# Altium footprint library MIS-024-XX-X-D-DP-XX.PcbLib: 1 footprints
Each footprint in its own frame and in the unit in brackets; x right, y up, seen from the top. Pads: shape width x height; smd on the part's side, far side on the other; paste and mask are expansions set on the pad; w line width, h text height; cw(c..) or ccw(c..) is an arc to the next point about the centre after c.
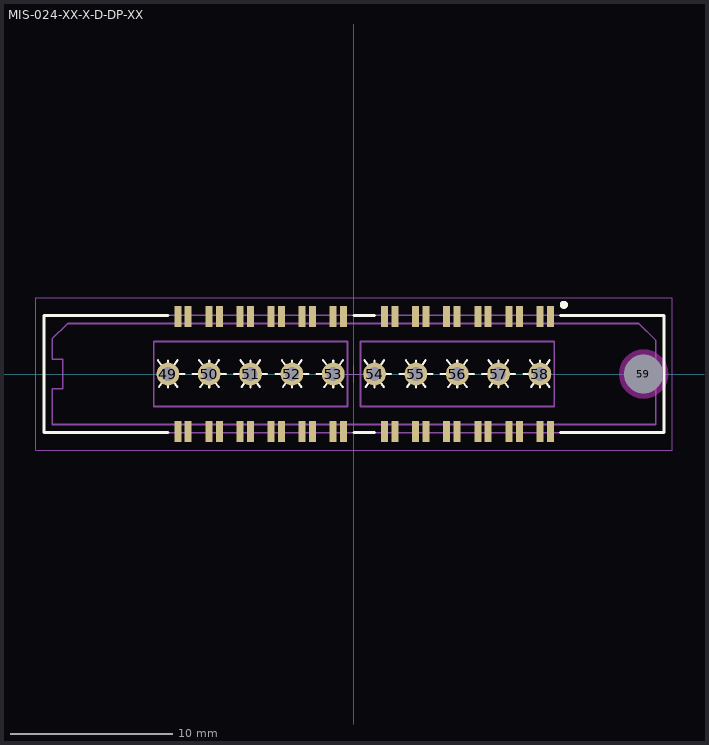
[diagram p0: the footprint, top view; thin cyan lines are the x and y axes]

## MIS-024-XX-X-D-DP-XX [mm] "0.635mm pitch, 48 pin, mixed technology high speed socket; differential"
height 3.63
pads (59):
  rect 0.43x1.3 smd mask+0: 1(12.07,3.53) 2(12.07,-3.53) 3(11.43,3.53) 4(11.43,-3.53) 5(10.16,3.53) 6(10.16,-3.53) 7(9.52,3.53) 8(9.52,-3.53) 9(8.25,3.53) 10(8.25,-3.53) 11(7.61,3.53) 12(7.61,-3.53) 13(6.34,3.53) 14(6.34,-3.53) 15(5.7,3.53) 16(5.7,-3.53) 17(4.43,3.53) 18(4.43,-3.53) 19(3.79,3.53) 20(3.79,-3.53) 21(2.52,3.53) 22(2.52,-3.53) 23(1.88,3.53) 24(1.88,-3.53) 25(-0.63,3.53) 26(-0.63,-3.53) 27(-1.27,3.53) 28(-1.27,-3.53) 29(-2.54,3.53) 30(-2.54,-3.53) 31(-3.18,3.53) 32(-3.18,-3.53) 33(-4.45,3.53) 34(-4.45,-3.53) 35(-5.09,3.53) 36(-5.09,-3.53) 37(-6.36,3.53) 38(-6.36,-3.53) 39(-7,3.53) 40(-7,-3.53) 41(-8.27,3.53) 42(-8.27,-3.53) 43(-8.91,3.53) 44(-8.91,-3.53) 45(-10.18,3.53) 46(-10.18,-3.53) 47(-10.82,3.53) 48(-10.82,-3.53)
  round 1.4 hole 0.85 mask+0: 49(-11.43,0) 50(-8.89,0) 51(-6.35,0) 52(-3.81,0) 53(-1.27,0) 54(1.27,0) 55(3.81,0) 56(6.35,0) 57(8.89,0) 58(11.43,0)
  round 1 hole 2.4 unplated mask+0: 59(17.78,0)
Top Overlay:
  circle w0.25: c12.9,4.25 r0.125
  lines w0.127: -12.05,0.845 -10.844,-0.806 ; -11.987,-0.806 -10.844,0.845 ; -11.43,-0.826 -11.43,0.826 ; -11.43,0 -10.414,0 ; -9.906,0 -7.874,0 ; -9.51,0.845 -8.304,-0.806 ; -9.447,-0.806 -8.304,0.845 ; -8.89,-0.826 -8.89,0.826 ; -7.366,0 -5.334,0 ; -6.97,0.845 -5.764,-0.806 ; -6.907,-0.806 -5.764,0.845 ; -6.35,-0.826 -6.35,0.826 ; -4.826,0 -2.794,0 ; -4.43,0.845 -3.224,-0.806 ; -4.367,-0.806 -3.224,0.845 ; -3.81,-0.826 -3.81,0.826 ; -2.286,0 -1.27,0 ; -1.89,0.845 -0.684,-0.806 ; -1.827,-0.806 -0.684,0.845 ; -1.27,-0.826 -1.27,0.826 ; 0.65,0.845 1.856,-0.806 ; 0.713,-0.806 1.856,0.845 ; 1.27,-0.826 1.27,0.826 ; 1.27,0 2.286,0 ; 2.794,0 4.826,0 ; 3.19,0.845 4.396,-0.806 ; 3.253,-0.806 4.396,0.845 ; 3.81,-0.826 3.81,0.826 ; 5.334,0 7.366,0 ; 5.73,0.845 6.936,-0.806 ; 5.793,-0.806 6.936,0.845 ; 6.35,-0.826 6.35,0.826 ; 7.874,0 9.906,0 ; 8.27,0.845 9.476,-0.806 ; 8.333,-0.806 9.476,0.845 ; 8.89,-0.826 8.89,0.826 ; 10.414,0 11.43,0 ; 10.81,0.845 12.016,-0.806 ; 10.873,-0.806 12.016,0.845 ; 11.43,-0.826 11.43,0.826
  lines w0.2: -11.445,-3.599 -19.045,-3.599 -19.045,3.601 -11.445,3.601 ; 0.005,-3.599 1.255,-3.599 ; 0.005,3.601 1.255,3.601 ; 12.705,-3.599 19.055,-3.599 19.055,3.601 12.705,3.601
Keep-Out Layer:
  pour cut-out: 19.307,0 19.278,0.294 19.193,0.577 19.053,0.837 18.866,1.066 18.637,1.253 18.377,1.393 18.094,1.478 17.8,1.507 17.506,1.478 17.223,1.393 16.963,1.253 16.734,1.066 16.547,0.837 16.407,0.577 16.322,0.294 16.293,0 16.322,-0.294 16.407,-0.577 16.547,-0.837 16.734,-1.066 16.963,-1.253 17.223,-1.393 17.506,-1.478 17.8,-1.507 18.094,-1.478 18.377,-1.393 18.637,-1.253 18.866,-1.066 19.053,-0.837 19.193,-0.577 19.278,-0.294
Mechanical 12:
  lines w0.001: -19.045,-3.599 19.055,-3.599 19.055,3.601 -19.045,3.601 -19.045,-3.599
Mechanical 13:
  lines w0.1: -19.045,-3.599 19.055,-3.599 19.055,3.601 -19.045,3.601 -19.045,-3.599 ; -18.545,-3.099 18.555,-3.099 18.555,-0.899 17.405,-0.899 17.405,0.901 18.555,0.901 18.555,2.064 17.498,3.101 -17.587,3.101 -18.545,2.161 -18.545,0.901 -17.895,0.901 -17.895,-0.899 -18.545,-0.899 -18.545,-3.099 ; -12.295,-1.999 -0.395,-1.999 -0.395,2.001 -12.295,2.001 -12.295,-1.999 ; 0.405,-1.999 12.305,-1.999 12.305,2.001 0.405,2.001 0.405,-1.999
  text ".Designator" at 0.254,0.254 h1.52
Mechanical 15:
  lines w0.05: -0.5,0 0.5,0 ; 0,-0.5 0,0.5 ; -19.545,-4.699 19.555,-4.699 19.555,4.701 -19.545,4.701 -19.545,-4.699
